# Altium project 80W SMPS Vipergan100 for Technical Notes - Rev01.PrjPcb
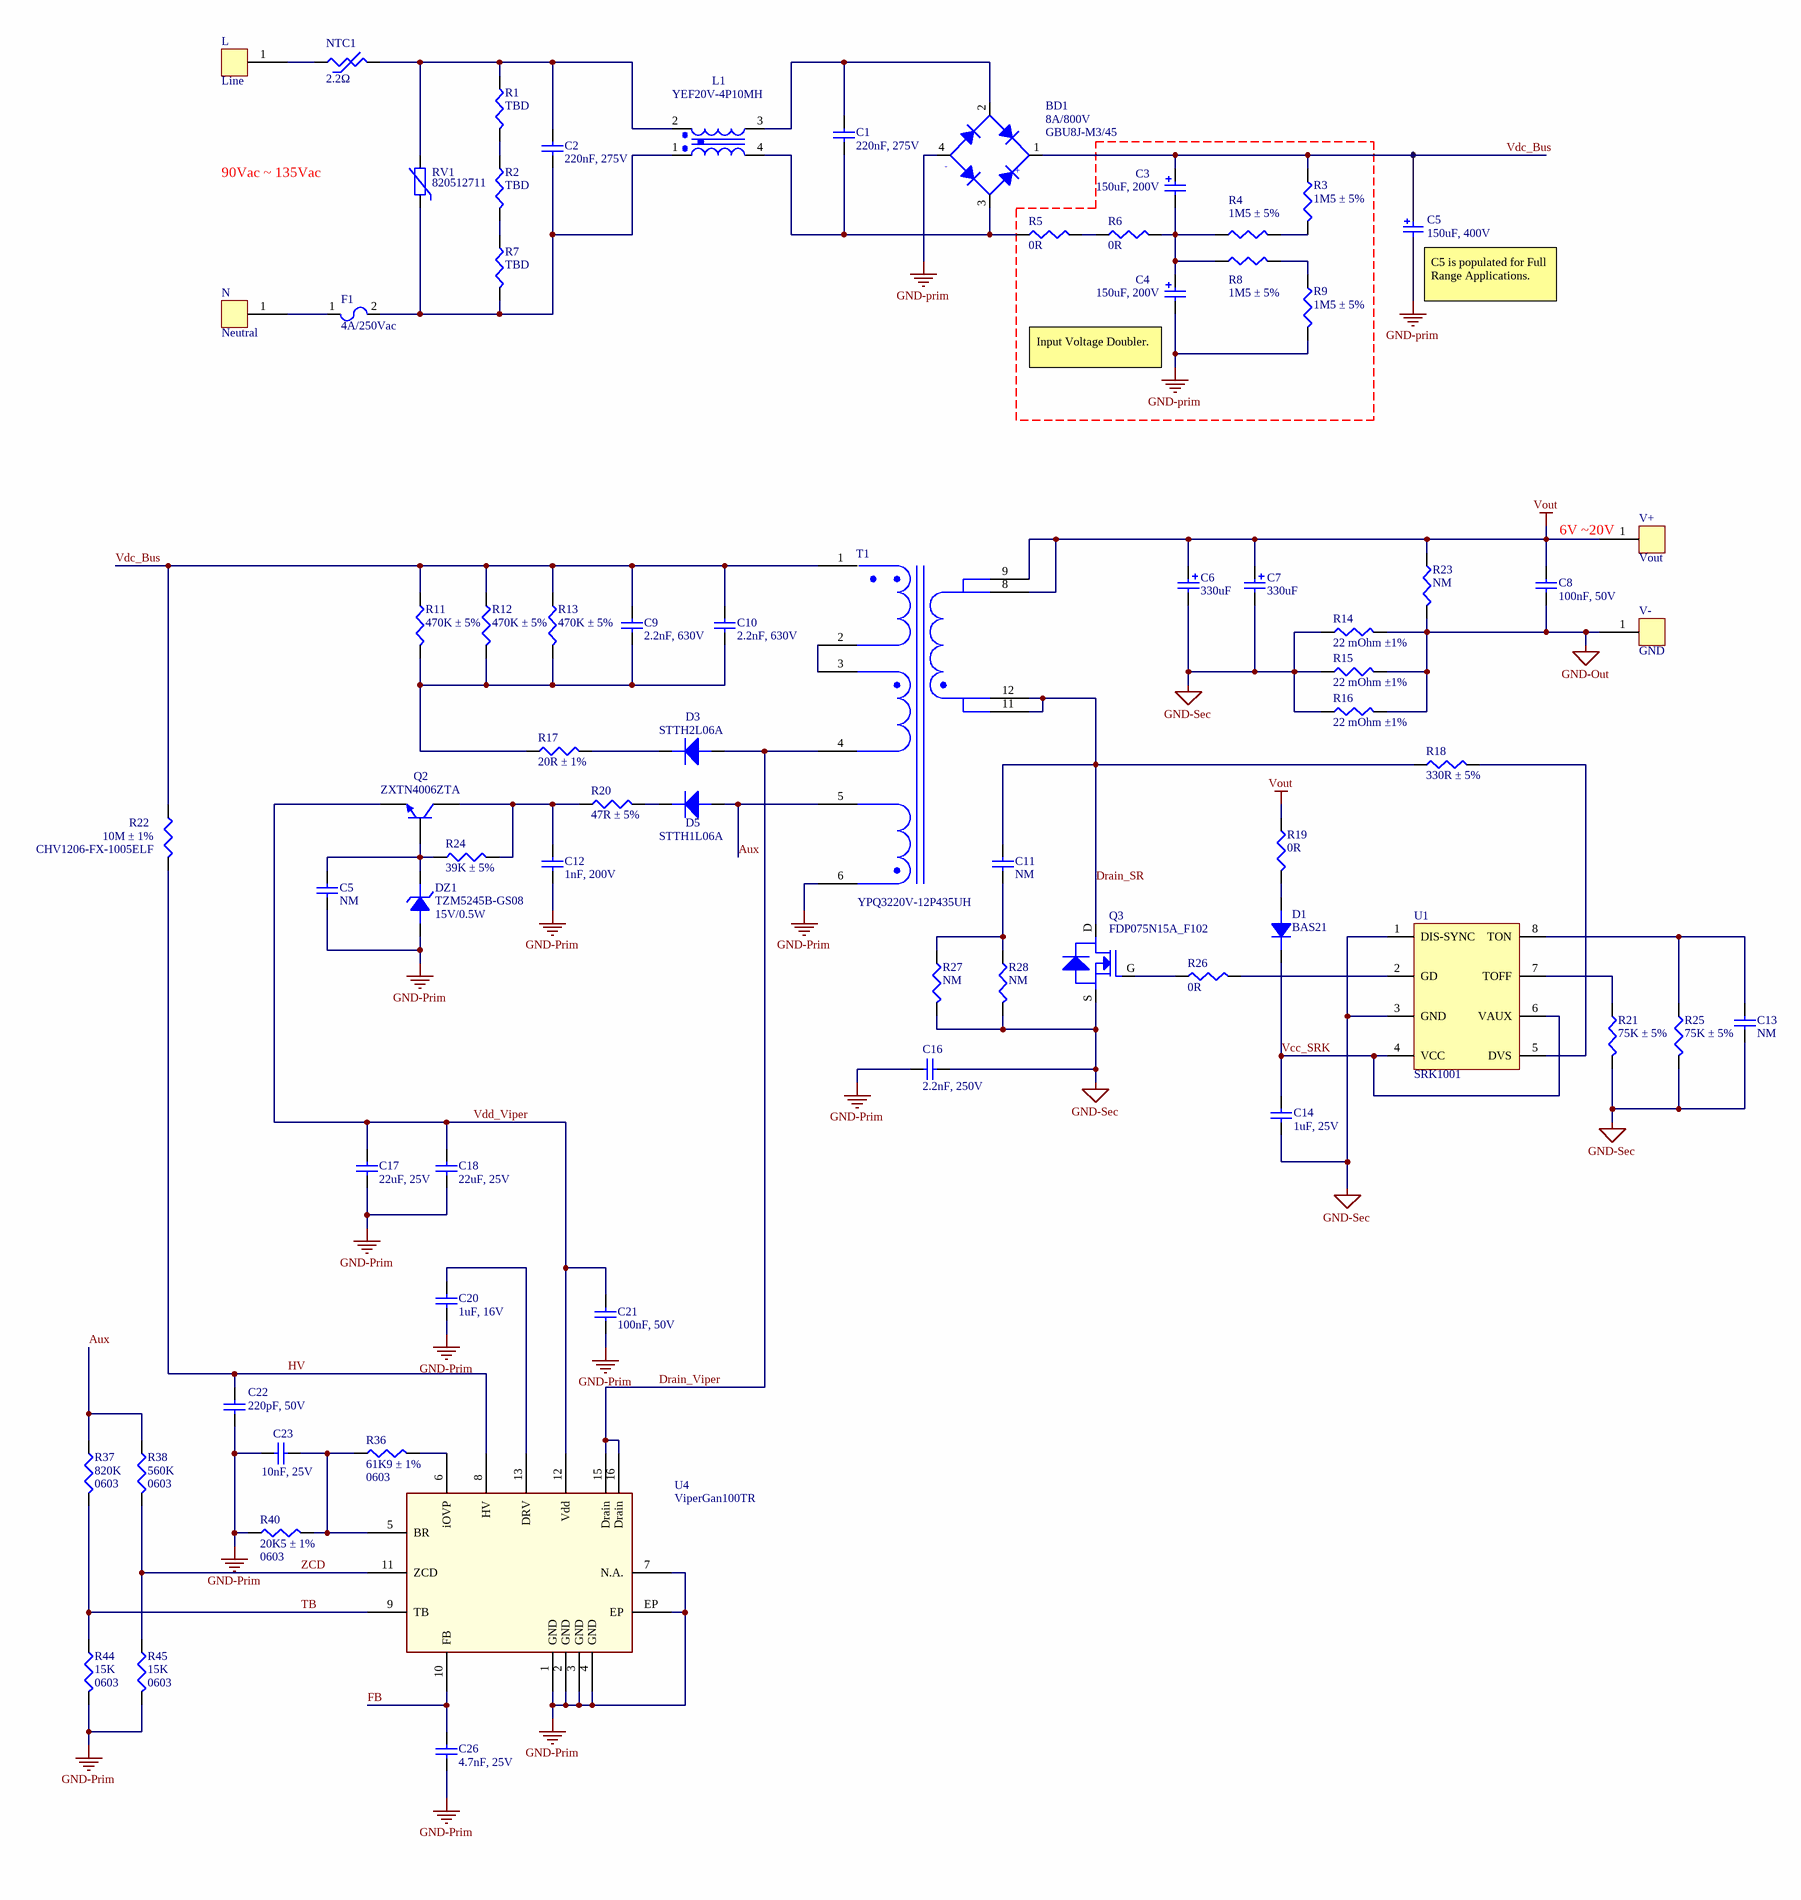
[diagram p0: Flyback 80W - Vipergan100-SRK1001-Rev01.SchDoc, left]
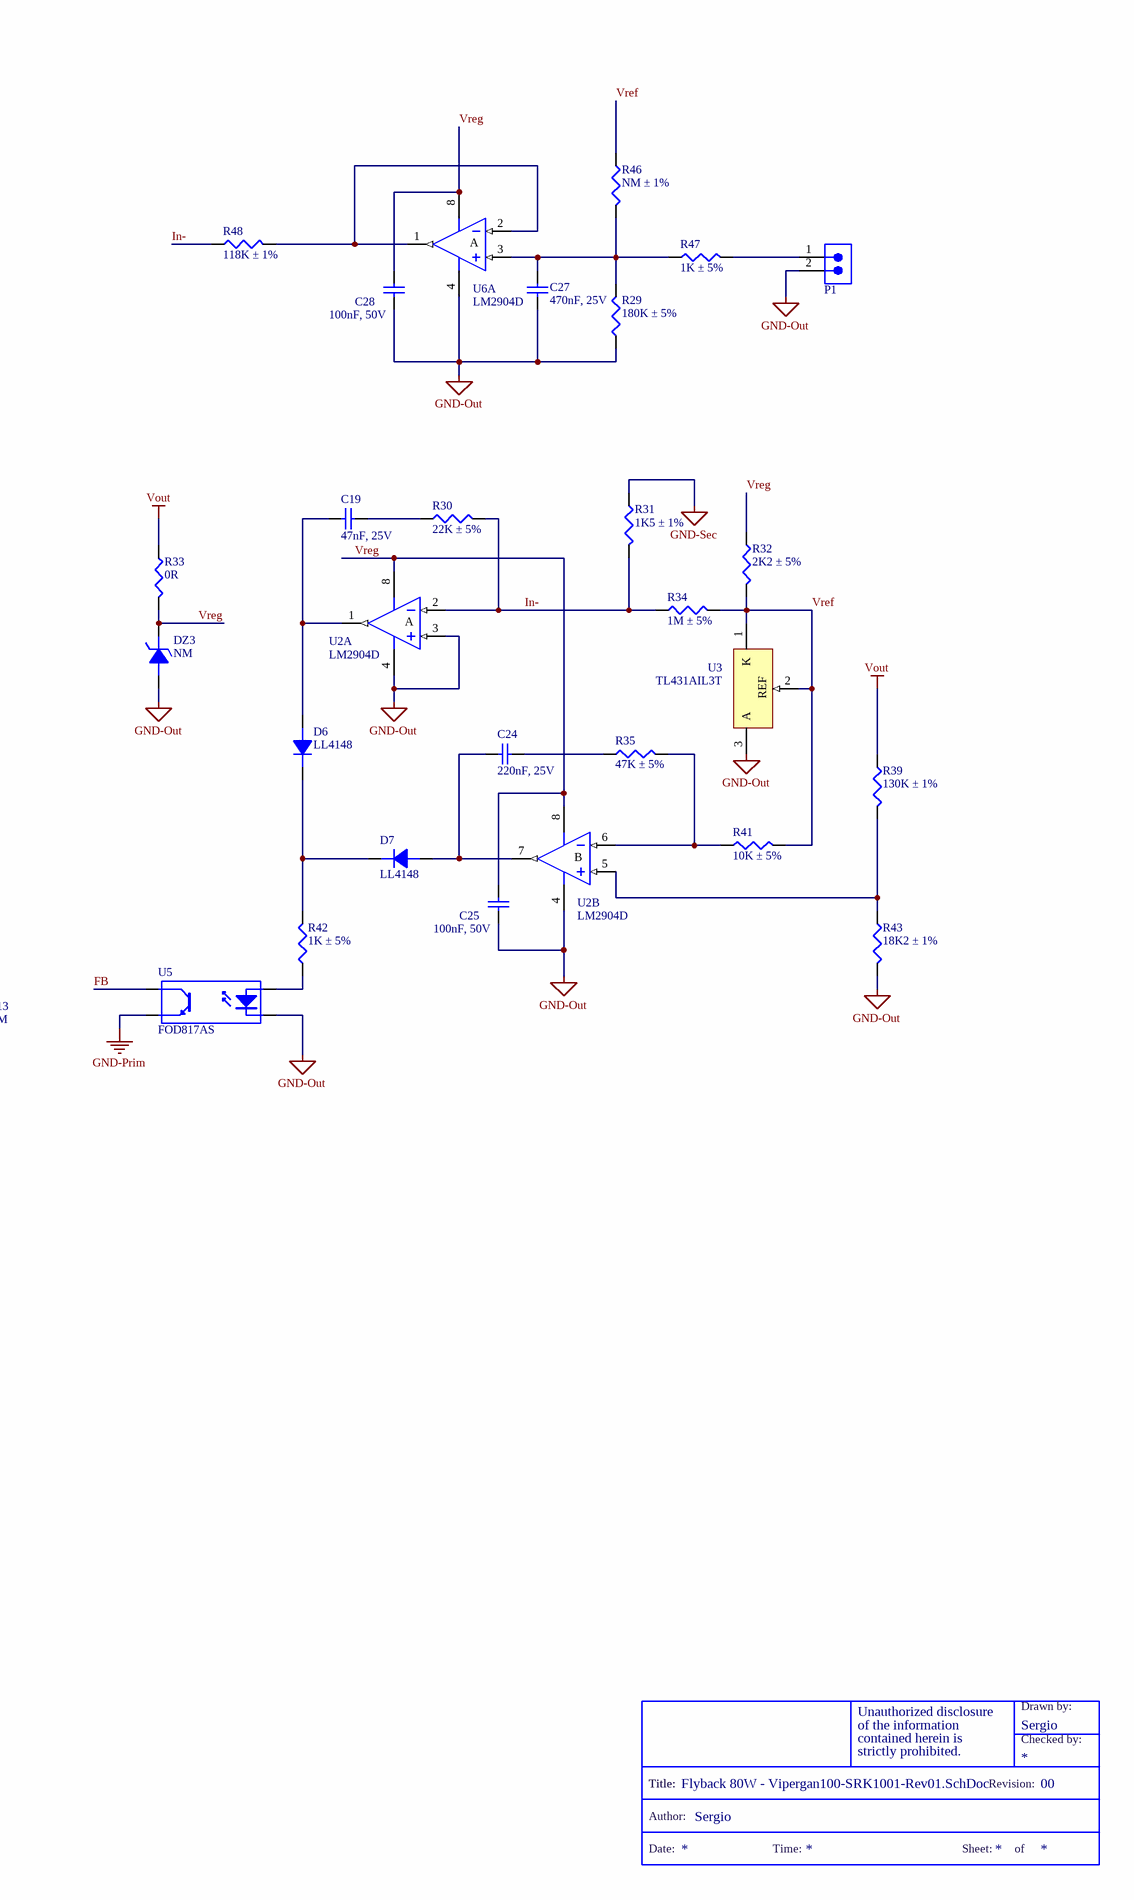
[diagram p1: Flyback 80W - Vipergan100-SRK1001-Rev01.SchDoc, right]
1 sheet, 101 parts. Net scope: global (net labels, ports and power ports of the same name join across sheets).
Board file: Flyback 80W - Vipergan100-SRK1001-Rev01.PcbDoc

## Sheet Flyback 80W - Vipergan100-SRK1001-Rev01.SchDoc
size A2; Author: Sergio; DrawnBy: Sergio; Revision: 00

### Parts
*?  Title_Block  (value not drawn)  (graphical)
BD1  8A/800V  Manufacturer Part Number: GBU8J-M3/45  [GBU806]
C1  220nF, 275V  [WCAP-FTX2_L18W6H11.5]
C2  220nF, 275V  [WCAP-FTX2_L18W6H11.5]
C3  150uF, 200V  [WCAP-AT1H_18x25]
C4  150uF, 200V  [WCAP-AT1H_18x25]
C5  NM  [WCAP-CSGP_0603_H=0.8mm_Reflow]
C6  330uF  [WCAP-PTG5_D10H12.5]
C7  330uF  [WCAP-PTG5_D10H12.5]
C8  100nF, 50V  [WCAP-CSGP_0603_H=0.8mm_Reflow]
C9  2.2nF, 630V  [WCAP-CSMH_1206_H1.6]
C10  2.2nF, 630V  [WCAP-CSMH_1206_H1.6]
C11  NM  [WCAP-CSGP_0805_H=0.8mm_Reflow]
C12  1nF, 200V  [WCAP-CSMH_0805_H1.25]
C13  NM  [WCAP-CSGP_0603_H=0.8mm_Reflow]
C14  1uF, 25V  [WCAP-CSGP_0805_H=1.25mm]
C16  2.2nF, 250V  [WCAP-CSSA_2211_H2.5]
C17  22uF, 25V  [WCAP-CSGP_1210_H=2.5mm]
C18  22uF, 25V  [WCAP-CSGP_1210_H=2.5mm]
C19  47nF, 25V  [WCAP-CSGP_0805_H=0.8mm_Reflow]
C20  1uF, 16V  [WCAP-CSGP_0603_H=0.8mm_Reflow]
C21  100nF, 50V  [WCAP-CSGP_0603_H=0.8mm_Reflow]
C22  220pF, 50V  [WCAP-CSGP_0603_H=0.8mm_Reflow]
C23  10nF, 25V  [WCAP-CSGP_0603_H=0.8mm_Reflow]
C24  220nF, 25V  [WCAP-CSGP_0603_H=0.8mm_Reflow]
C25  100nF, 50V  [WCAP-CSGP_0603_H=0.8mm_Reflow]
C26  4.7nF, 25V  [WCAP-CSGP_0603_H=0.8mm_Reflow]
C27  470nF, 25V  [WCAP-CSGP_0603_H=0.8mm_Reflow]
C28  100nF, 50V  [WCAP-CSGP_0603_H=0.8mm_Reflow]
D1  BAS21  [SOT23_Single]
D3  STTH2L06A  [SMA]
D5  STTH1L06A  [SMA]
D6  LL4148  [SOD80]
D7  LL4148  [SOD80]
DZ1  TZM5245B-GS08  value 15V/0.5W  [SOD80]
DZ3  NM  [SOD80]
F1  4A/250Vac  [MRT]
L  Line  [Pin_Hole_50mil]
L1  YEF20V-4P10MH  [EF20VCD4T-F]
N  Neutral  [Pin_Hole_50mil]
NTC1  2.2Ω  [D11.5xW5.0xH16.0xL5.0]
P1  61300211121  [61300211121]  (value not drawn)
Q2  ZXTN4006ZTA  [SOT-89 - BCE]
Q3  FDP075N15A_F102  [NFET_TO220FP]
R1  TBD  [0805]
R2  TBD  [0805]
R3  1M5 ± 5%  [0805]
R4  1M5 ± 5%  [0805]
R5  0R  [1206]
R6  0R  [1206]
R7  TBD  [0805]
R8  1M5 ± 5%  [0805]
R9  1M5 ± 5%  [0805]
R11  470K ± 5%  [2010]
R12  470K ± 5%  [2010]
R13  470K ± 5%  [2010]
R14  22 mOhm ±1%  [2512]
R15  22 mOhm ±1%  [2512]
R16  22 mOhm ±1%  [2512]
R17  20R ± 1%  [1206]
R18  330R ± 5%  [0603 - teste]
R19  0R  [0603 - teste]
R20  47R ± 5%  [0805]
R21  75K ± 5%  [0603 - teste]
R22  10M ± 1%  Manufacturer Part Number: CHV1206-FX-1005ELF  [1206]
R23  NM  [1206]
R24  39K ± 5%  [0603 - teste]
R25  75K ± 5%  [0603 - teste]
R26  0R  [0805]
R27  NM  [2010]
R28  NM  [2010]
R29  180K ± 5%  [0603 - teste]
R30  22K ± 5%  [0603 - teste]
R31  1K5 ± 1%  [0603 - teste]
R32  2K2 ± 5%  [1206]
R33  0R  [SM/R_0805]
R34  1M ± 5%  [0603 - teste]
R35  47K ± 5%  [0603 - teste]
R36  61K9 ± 1%  Case/Package: 0603  [SM/R_0603]
R37  820K  Case/Package: 0603  [SM/R_0603]
R38  560K  Case/Package: 0603  [SM/R_0603]
R39  130K ± 1%  [0603 - teste]
R40  20K5 ± 1%  Case Code (Imperial): 0603  [SM/R_0603]
R41  10K ± 5%  [0603 - teste]
R42  1K ± 5%  [0603 - teste]
R43  18K2 ± 1%  [0603 - teste]
R44  15K  Case Code (Imperial): 0603  [SM/R_0603]
R45  15K  Case Code (Imperial): 0603  [SM/R_0603]
R46  NM ± 1%  [0603 - teste]
R47  1K ± 5%  [0603 - teste]
R48  118K ± 1%  [0603 - teste]
RV1  820512711  [D12.5xW6.5xH16xP1.3]
T1  YPQ3220V-12P435UH  [PQ3220_Trigon]
U1  SRK1001  [SO8_L]
U2  LM2904D  [SO8_N]  (parts A,B of 2)
U3  TL431AIL3T  [SOT23-3_N]
U4  ViperGan100TR  [ViperGan - ISac]
U5  FOD817AS  [SO-4]
U6  LM2904D  [SO8_N]  (part A of 2)
V+  Vout  [Pin_Hole_75mil]
V-  GND  [Pin_Hole_75mil]

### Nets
GND-Out: C8.1 C25.1 C27.1 C28.1 DZ3.A(ANODE) P1.2 R14.2 R15.2 R16.2 R23.2 R29.1 R43.2 U2.3(IN+) U2.4(V-) U3.3(A) U5.2(K) U6.4(V-) V-.1
GND-Prim: BD1.4(DC_OUT_MINUS) C4.1(N) C5.1 C12.1 C16.1 C17.1 C18.1 C20.1 C21.1 C22.1 C23.1 C26.1 DZ1.A(ANODE) R9.2 R40.1 R44.2 R45.2 T1.6 U4.1(GND) U4.2(GND) U4.3(GND) U4.4(GND) U4.7(N.A.) U4.EP U5.3(E)
GND-Sec: C6.2(N) C7.2(N) C13.1 C14.1 C16.2 Q3.S(SOURCE) R14.1 R15.1 R16.1 R21.2 R25.2 R27.2 R28.2 R31.1 U1.1(DIS-SYNC) U1.3(GND)
Vout: C6.1(P) C7.1(P) C8.2 R19.1 R23.1 R33.1 R39.1 T1.8 T1.9 V+.1
Aux: D5.A R37.1 R38.1 T1.5
Drain_SR: C11.2 Q3.D(DRAIN) R18.1 T1.11 T1.12
Drain_Viper: D3.A T1.4 U4.15(Drain) U4.16(Drain)
FB: C26.2 U4.10(FB) U5.4(C)
HV: C22.2 R22.2 U4.8(HV)
In-: R30.2 R31.2 R34.1 R48.1 U2.2(IN-)
TB: R37.2 R44.1 U4.9(TB)
Vcc_SRK: C14.2 D1.K(CATHODE) U1.4(VCC) U1.6(VAUX)
Vdc_Bus: BD1.1(DC_OUT_PLUS) C3.2(P) C9.2 C10.2 R3.1 R11.1 R12.1 R13.1 R22.1 T1.1
Vdd_Viper: C17.2 C18.2 C21.2 Q2.E U4.12(Vdd)
Vref: R32.2 R34.2 R41.2 R46.1 U3.1(K) U3.2(REF)
Vreg: C25.2 C28.2 DZ3.K(CATHODE) R32.1 R33.2 U2.8(V+) U6.8(V+)
ZCD: R38.2 R45.1 U4.11(ZCD)
NetBD1_2: BD1.2(AC_IN_1) C1.1 L1.3
NetBD1_3: BD1.3(AC_IN_2) C1.2 L1.4 R5.1
NetC2_1: C2.1 L1.2 NTC1.2 R1.1 RV1.2
NetC2_2: C2.2 F1.2 L1.1 R7.2 RV1.1
NetC3_1: C3.1(N) C4.2(P) R4.1 R6.2 R8.1
NetC5_2: C5.2 DZ1.K(CATHODE) Q2.B R24.1
NetC9_1: C9.1 C10.1 R11.2 R12.2 R13.2 R17.1
NetC11_1: C11.1 R27.1 R28.1
NetC12_2: C12.2 Q2.C R20.1 R24.2
NetC13_2: C13.2 R25.1 U1.8(TON)
NetC19_1: C19.1 R30.1
NetC19_2: C19.2 D6.A(ANODE) U2.1(OUT)
NetC20_2: C20.2 U4.13(DRV)
NetC23_2: C23.2 R36.1 R40.2 U4.5(BR)
NetC24_1: C24.1 D7.A(ANODE) U2.7(OUT)
NetC24_2: C24.2 R35.1
NetC27_2: C27.2 R29.2 R46.2 R47.1 U6.3(IN+)
NetD1_A: D1.A(ANODE) R19.2
NetD3_K: D3.K R17.2
NetD5_K: D5.K R20.2
NetD6_K: D6.K(CATHODE) D7.K(CATHODE) R42.2
NetF1_1: F1.1 N.1
NetL_1: L.1 NTC1.1
NetP1_1: P1.1 R47.2
NetQ3_G: Q3.G(GATE) R26.1
NetR1_2: R1.2 R2.1
NetR2_2: R2.2 R7.1
NetR3_2: R3.2 R4.2
NetR5_2: R5.2 R6.1
NetR8_2: R8.2 R9.1
NetR18_2: R18.2 U1.5(DVS)
NetR21_1: R21.1 U1.7(TOFF)
NetR26_2: R26.2 U1.2(GD)
NetR35_2: R35.2 R41.1 U2.6(IN-)
NetR36_2: R36.2 U4.6(iOVP)
NetR39_2: R39.2 R43.1 U2.5(IN+)
NetR42_1: R42.1 U5.1(A)
NetR48_2: R48.2 U6.1(OUT) U6.2(IN-)
NetT1_2: T1.2 T1.3

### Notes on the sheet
- 90Vac ~ 135Vac
- C5
- 150uF, 400V
- C5 is populated for Full Range Applications.
- (near C4) Input Voltage Doubler.
- 6V |0V
- Labels drawn without touching a wire or pin: GND-prim

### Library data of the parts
BD1 = GBU806: 800V 8A Glass Passivated Single-Phase Bridge Rectifier; Manufacturer: Vishay; Value/Generic Part Number: GBU8J; Package/Class: Full wave bridge; Max Reverse Current: 5uA; Max Surge Current: 150A
C1 C2 = 890324025027: WCAP-FTX2 Film Capacitor, THT, L18W6H11.5, 220nF, 275V; Manufacturer: Wurth Elektronik; Insulation Resistance: 30000MOhm; Dissipation Factor@100kHz: 2%; Dissipation Factor@1kHz: 0.1%; Dissipation Factor@10kHz: 0.2%; Rated Voltage: 275VAC; Rate of Voltage Rise: 180V/us; Pitch: 15mm; Technical Reference: MX2P015224K275ASPB15000; Capacitance Tolerance: +/-10%
C3 C4 = 860241081008: WCAP-AT1H Aluminum Electrolytic Capacitor, Radial, THT, D18xH25mm, 150uF, 200V; Manufacturer: Wurth Elektronik; Dissipation Factor: 15%; Endurance: 10000h; Leakage Current: 1300uA; Ripple Current: 1800mA; Capacitance Tolerance: +/-20%; Rated Voltage: 200VDC; Technical Reference: ATJL250151M200DSPAEK000
C5 C8 C21 C25 C28 = 885012206095: WCAP-CSGP Multilayer Ceramic Chip Capacitor, General Purpose, size 0603, X7R, 100nF, 50V; Manufacturer: Wurth Elektronik; Rated Voltage: 50VDC; Isolation Resistance: >=5GOhm; Capacitance Tolerance: +/-10%; Technical Reference: X7R0603104K050DFCT10000
C6 C7 = 870025575009: WCAP-PTG5 Aluminum Polymer Capacitor, Radial THT, D10xH12.5mm, 330uF, 25V; Manufacturer: Wurth Elektronik; Capacitance Tolerance: +/-20%; Dissipation Factor: 8%; Endurance: 2000h; ESR: 20mOhm; Leakage Current: 1650uA; Ripple Current: 4900mA; Technical Reference: PTEF125331M025DSPA9B000
C9 C10 = 885342008007: WCAP-CSMH Multilayer Ceramic Chip Capacitor, size 1206, NP0 Class I, 2.2nF, 630V; Manufacturer: Wurth Elektronik; Rated Voltage: 630VDC; Insulation Resistance: 10GOhm; Capacitance Tolerance: +/-5%; Technical Reference: NP01206222J630DFCT10000
C11 = 885012207119: WCAP-CSGP Multilayer Ceramic Chip Capacitor, General Purpose, size 0805, X7R, 3.3nF, 100V; Manufacturer: Wurth Elektronik; Rated Voltage: 100VDC; Isolation Resistance: >=10GOhm; Capacitance Tolerance: +/-10%; Technical Reference: X7R0805332K100DFCT10000
C12 = 885342007003: WCAP-CSMH Multilayer Ceramic Chip Capacitor, size 0805, NP0 Class I, 1nF, 200V; Manufacturer: Wurth Elektronik; Rated Voltage: 200VDC; Insulation Resistance: 10GOhm; Capacitance Tolerance: +/-5%; Technical Reference: NP00805102J200DFCT10000
C13 = 885012206071: WCAP-CSGP Multilayer Ceramic Chip Capacitor, General Purpose, size 0603, X7R, 100nF, 25V; Manufacturer: Wurth Elektronik; Rated Voltage: 25VDC; Isolation Resistance: >=5GOhm; Capacitance Tolerance: +/-10%; Technical Reference: X7R0603104K025DFCT10000
C14 = 885012207078: WCAP-CSGP Multilayer Ceramic Chip Capacitor, General Purpose, size 0805, X7R, 1uF, 25V; Manufacturer: Wurth Elektronik; Rated Voltage: 25VDC; Isolation Resistance: >=0.5GOhm; Capacitance Tolerance: +/-10%; Technical Reference: X7R0805105K025DFCT10000
C16 = 885352213015: WCAP-CSSA Multilayer Ceramic Chip Safety Capacitor, size 2211, X1/Y2, 2.2nF, 250V; Manufacturer: Wurth Elektronik; Impulse Voltage: 5000VDC; Ceramic Type: X7R Class II; Dissipation Factor: 2.5%; Isolation Resistance: 10GOhm; Rated Voltage: 250VAC; Capacitance Tolerance: +/-10%; Technical Reference: X7R2211222KE00IFCT10000
C17 C18 = 885012209074: WCAP-CSGP Multilayer Ceramic Chip Capacitor, General Purpose, size 1210, X7R, 22uF, 25V; Manufacturer: Wurth Elektronik; Rated Voltage: 25VDC; Isolation Resistance: >=0.005GOhm; Capacitance Tolerance: +/10%; Technical Reference: X7R1210226K025DFCT10000
C19 = 885012207070: WCAP-CSGP Multilayer Ceramic Chip Capacitor, General Purpose, size 0805, X7R, 47nF, 25V; Manufacturer: Wurth Elektronik; Rated Voltage: 25VDC; Isolation Resistance: >=10GOhm; Capacitance Tolerance: +/-10%; Technical Reference: X7R0805473K025DFCT10000
C20 = 885012206052: WCAP-CSGP Multilayer Ceramic Chip Capacitor, General Purpose, size 0603, X7R, 1uF, 16V; Manufacturer: Wurth Elektronik; Rated Voltage: 16VDC; Isolation Resistance: >=0.1GOhm; Capacitance Tolerance: +/-10%; Technical Reference: X7R0603105K016DFCT10000
C22 = 885012206079: WCAP-CSGP Multilayer Ceramic Chip Capacitor, General Purpose, size 0603, X7R, 220pF, 50V; Manufacturer: Wurth Elektronik; Rated Voltage: 50VDC; Isolation Resistance: >=10GOhm; Capacitance Tolerance: +/-10%; Technical Reference: X7R0603221K050DFCT10000
C23 = 885012206065: WCAP-CSGP Multilayer Ceramic Chip Capacitor, General Purpose, size 0603, X7R, 10nF, 25V; Manufacturer: Wurth Elektronik; Rated Voltage: 25VDC; Isolation Resistance: >=10GOhm; Capacitance Tolerance: +/-10%; Technical Reference: X7R0603103K025DFCT10000
C24 C27 = 885012206075: WCAP-CSGP Multilayer Ceramic Chip Capacitor, General Purpose, size 0603, X7R, 470nF, 25V; Manufacturer: Wurth Elektronik; Rated Voltage: 25VDC; Isolation Resistance: >=1.1GOhm; Capacitance Tolerance: +/-10%; Technical Reference: X7R0603474K025DFCT10000
C26 = 885012206063: WCAP-CSGP Multilayer Ceramic Chip Capacitor, General Purpose, size 0603, X7R, 4.7nF, 25V; Manufacturer: Wurth Elektronik; Rated Voltage: 25VDC; Isolation Resistance: >=10GOhm; Capacitance Tolerance: +/-10%; Technical Reference: X7R0603472K025DFCT10000
D1 = BAS21: High Speed Switching Diode 250V 0.25A 3-Pin SOT-23 T/R; Manufacturer: Diodes; Value: 250V/200mA
D3 = SMA: 600 V, 2 A Low Drop Ultrafast Diode.; Manufacturer: STMicroelectronics; Value: 1A/600V
D5 = SMA: 600 V, 1 A Low Drop Ultrafast Diode.; Manufacturer: STMicroelectronics; Value: 1A/600V
D6 D7 = LL4148: Small Signal Diode; Manufacturer Part Number: LL4148-M-18; Manufacturer: Vishay; Value: 100V 150mA
DZ1 = TZM52xxB: Small Signal Zener Diodes, 5%, 500mW; Manufacturer: Vishay
DZ3 = SOD80_zener
F1 = Fuse: FUSE BOARD MOUNT 4A 250VAC RAD; Manufacturer: Littelfuse Wickmann; Manufacturer Part Number: 37314000410; Color: Brown; Voltage Rating (AC): 250V; Fuse Type: Board Mount (Cartridge Style Excluded); Power Dissipation: 520mW; DC Cold Resistance: 18.52mR; Approvals: UL,CSA
L N = Pin_Hole_50mil
L1 = EF20VCD4T-F_Transfonte_Esquema2: Manufacturer: Trigon Components
NTC1 = B57236S0229M000: Inrush Current Limiter, Diameter 11.5mm, Width 5.0mm, Height 16.0mm, Leads 5.0mm, 2.2Ω, 6 / 5A; Manufacturer: TDK; Resistance Tolerance: ±20%; Max. Current: 6 / 5A
P1 = 61300211121: WR-PHD Pin Header, THT, Vertical, pitch 2.54mm, 1 Row, 2P; Manufacturer: Wurth Elektronik; Contact Resistance: 20mΩ; Rated Current: 3A; Working Voltage: 250V; Withstanding Voltage: 500V
Q2 = NPN: 200V, 1A NPN LED DRIVING TRANSISTOR IN SOT89; Manufacturer: Diodes; Value: 200V/1A
Q3 = NFET: N-Channel Mosfet, 150V, 130A, 7.5m Ohms.; Manufacturer: ONSEMI
R1-R4 R7-R9 R20 R26 = 0805: SMD Chip Resistor, 200 mW, 0805 [2012 Metric], Thick Film, General Purpose; Manufacturer: Any
R5 R6 R17 R23 R32 = 1206: SMD Chip Resistor, 250 mW, 1206 [3216 Metric], Thick Film, General Purpose; Manufacturer: Any
R11-R13 = 2010: SMD Chip Resistor, 1W, 2010, Thick Film, General Purpose; Manufacturer: Yageo; Manufacturer Part Number: RC2010JK-07470KL
R14-R16 = 2512: SMD Chip Resistor, 2512, High Power Metal Strip Resistors for Current Sensing.; Manufacturer: TE Connectivity; Manufacturer Part Number: TLRP3A30DR022FTE
R18 = 0603: SMD Chip Resistor, 125 mW,  0603 [1608 Metric] 330 Ohm, Thick Film, General Purpose; Manufacturer: Any
R19 R21 R24 R25 R29-R31 R34 R35 R39 R41-R43 R46-R48 = 0603: SMD Chip Resistor, 125 mW, 0603 [1608 Metric], Thick Film, General Purpose; Manufacturer: Any
R22 = 1206: SMD Chip Resistor, 250 mW, 1206 [3216 Metric], Thick Film, General Purpose; Manufacturer: Bourns
R27 R28 = 2010: SMD Chip Resistor, 1W, 2010, Thick Film, General Purpose; Manufacturer: Any
R33 = SMRes: SMD Chip Resistor, 250 mW, 1206 [3216 Metric], Thick Film, General Purpose; Manufacturer Part Number: CRCW1206-10R0FKEA; Resistance: 10R; Tolerance: 1%; Temperature Coefficient: 100ppm/°C; Max Power Dissipation: 250mW; Voltage Rating (DC): 200V
R36 = SMRes: Res Thick Film 0603 61.9K Ohm 1% 1/10W ±100ppm/°C Molded SMD SMD Paper T/R; Manufacturer: Any; Manufacturer Part Number: CRCW060356K0FKEA; Max Power Dissipation: 100mW; Voltage Rating (DC): 75V
R37 = SMRes: Res Thick Film 0603 180K Ohm 1% 1/10W ±100ppm/°C Molded SMD SMD Paper T/R; Manufacturer Part Number: CRCW0603180KFKEA; Resistance: 180kR; Max Power Dissipation: 100mW; Voltage Rating: 75V
R38 = SMRes: Res Thick Film 0603 120K Ohm 1% 0.1W(1/10W) ±100ppm/°C Pad SMD Automotive T/R; Manufacturer Part Number: CRCW0603120KFKEA; Resistance: 120kR; Max Power Dissipation: 100mW; Voltage Rating (DC): 75V
R40 = SMRes: Res Thick Film 0603 20.5K Ohm 1% 1/10W ±100ppm/°C Molded SMD Paper T/R; Manufacturer: Any; Manufacturer Part Number: CRCW060315K0FKEA; Power Rating: 100mW; Voltage Rating: 75V
R44 R45 = SMRes: Res Thick Film 0603 15K Ohm 1% 1/10W ±100ppm/°C Molded SMD Paper T/R; Manufacturer Part Number: CRCW060315K0FKEA; Resistance: 15kR; Power Rating: 100mW; Voltage Rating: 75V
RV1 = 820512711: WE-VD Disk Varistor, D12.5mm, W6.5mm, H16mm, 275VAC, 350VDC; Manufacturer: Wurth Elektronik; (Channel) Input Capacitance: 190pF; (Reverse) Peak Pulse Current: 2500A; (Reverse) Breakdown Voltage: 430V; Clamping Voltage: 710V; AC Operating Voltage: 275V; DC Operating Voltage: 350V; Energy Absorbtion: 66J; Power Dissipation: 0.4W
T1 = PQ3220, ViperGan100: Transformer 12-Terminal , THT, Vertical, PQ Style Bobbins, PQ3220; Manufacturer: Trigon Components
U1 = SRK1001: Adaptive synchronous rectification controller for flyback converter; Manufacturer: STMicroelectronics
U2 U6 = LM2904D: Low-Power Dual Operational Amplifier
U3 = TL431AIL3T: STMICROELECTRONICS - TL431AIL3T - Voltage Reference, AEC-Q100, Shunt - Adjustable, 2.5V to 36V, 1 % Ref, SOT-23-3; Max Input Voltage: 37V; Max Output Current: 100mA; Reference Type: Shunt,Adjustable; Tolerance: 1%; Number of Channels: 1; Cathode Current: 700uA; Reference Voltage: 2.495V
U4 = ViperGanxxx: Advanced quasi-resonant offline high voltage converter with E-mode GaN HEMT.; Manufacturer: STMicroelectronics; Value: QR Controller
U5 = Optoisolator1: Optocoupler DC-IN 1-CH Transistor DC-OUT 4-Pin PDIP SMD Black T/R; Manufacturer: ONSEMI; Number of Channels: 1; Max Output Voltage: 80V; Output Current per Channel: 50mA; Forward Voltage: 1.2V; Collector Emitter Voltage (VCEO): 200mV; Rise Time: 18000ns; Max Power Dissipation: 200mW; Output Voltage: 70V; Reverse Breakdown Voltage: 6V; Isolation Voltage: 5kV; Current Transfer Ratio: 160%; Input Type: DC
V+ V- = Pin_Hole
